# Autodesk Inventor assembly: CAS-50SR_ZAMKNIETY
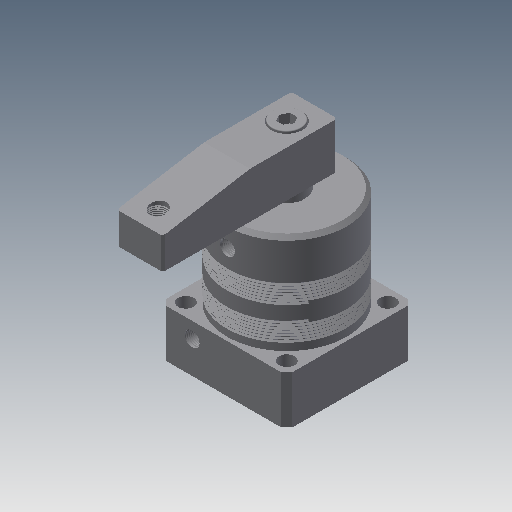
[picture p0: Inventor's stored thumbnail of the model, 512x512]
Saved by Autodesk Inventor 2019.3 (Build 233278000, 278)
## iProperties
Created: 2009-09
Part Number: CAS-50SR_ZAMKNIETY
Material: Ogólny
Document SubType Name: Assembly
Designer: CADENGINEERING4
Sending System: PRO/ENGINEER BY PARAMETRIC TECHNOLOGY CORPORATION, 2007170
Preprocessor: PRO/ENGINEER BY PARAMETRIC TECHNOLOGY CORPORATION, 2007170
Title: CAS-50S_ASM
Author: Administrator
Revision Number: 1LAST_VERSION
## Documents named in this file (7)
- D:\Vault_2016\Projekty\STRONA\Pneumatic\Line ; Pipe connecct - type\cas-50s_asm\CAS-50SR_ZAMKNIETY.iam
- D:\Vault_2016\Projekty\STRONA\Pneumatic\Line ; Pipe connecct - type\cas-50s_asm\CAS-50BT.ipt
- D:\Vault_2016\Projekty\STRONA\Pneumatic\Line ; Pipe connecct - type\cas-50s_asm\CAS-50SHSG.ipt
- D:\Vault_2016\Projekty\STRONA\Pneumatic\Line ; Pipe connecct - type\cas-50s_asm\CAS-50HG.ipt
- D:\Vault_2016\Projekty\STRONA\Pneumatic\Line ; Pipe connecct - type\cas-50s_asm\M4.ipt
- D:\Vault_2016\Projekty\STRONA\Pneumatic\Line ; Pipe connecct - type\cas-50s_asm\CAS-50SYB.ipt
- D:\Vault_2016\Projekty\STRONA\Pneumatic\Line ; Pipe connecct - type\cas-50s_asm\M10LC.ipt
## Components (9 placed, 9 different names)
1. CAS-50BT_0 — Zestawiające:5, Kątowe:1, Równoległe:1
2. CAS-50SHSG_1 — Zestawiające:1, Zestawiające:2, Zestawiające:4, Zestawiające:5
3. CAS-50HG_2
4. M4_3
5. M4_4
6. M4_5
7. M4_6
8. CAS-50SYB_7 — Zestawiające:1, Zestawiające:3, Zestawiające:4, Kątowe:1, Równoległe:1
9. M10LC_8 — Zestawiające:2, Zestawiające:3
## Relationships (7: Mate 5, Angle 1, Flush 1)
- Zestawiające:1 [Mate]: CAS-50SHSG_1 ↔ CAS-50SYB_7
- Zestawiające:2 [Mate]: CAS-50SHSG_1 ↔ M10LC_8
- Zestawiające:3 [Mate]: CAS-50SYB_7 ↔ M10LC_8
- Zestawiające:4 [Mate]: CAS-50SHSG_1 ↔ CAS-50SYB_7
- Zestawiające:5 [Mate]: CAS-50BT_0 ↔ CAS-50SHSG_1
- Kątowe:1 [Angle]: CAS-50BT_0 ↔ CAS-50SYB_7
- Równoległe:1 [Flush]: CAS-50BT_0 ↔ CAS-50SYB_7
